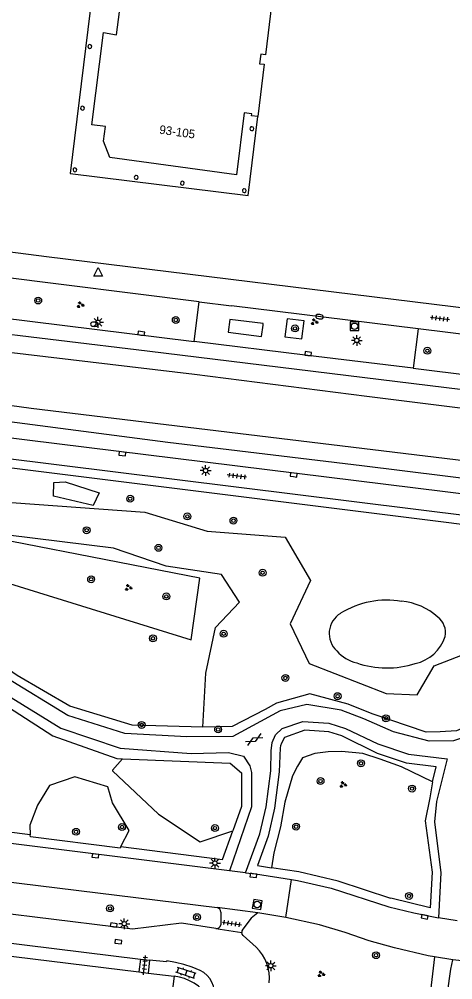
# Model space of a CAD drawing. Extents: x 131000 to 133014, y 396499 to 399001.
# Drawn here: x 131782.7 to 131833, y 396928.8 to 397040.1 of the extents above; entities that cross this region are included whole.
import ezdxf

# ---------------------------------------------------------------- set-up
doc = ezdxf.new("R2010")
doc.units = 0
for name, color, linetype in [('gg-anno-huisnummerreeks BGT', 7, 'Continuous'), ('gg-bbg-abri', 7, 'Continuous'), ('gg-bbg-hoofdgebouw', 7, 'Continuous'), ('gg-bbg-onder overbouw', 7, 'Continuous'), ('gg-bbg-pand overbouw', 7, 'Continuous'), ('gg-bbg-pilaar onder overbouw', 7, 'Continuous'), ('gg-knt-verharding', 7, 'Continuous'), ('gg-knt-verharding nz', 7, 'Continuous'), ('gt-grn-groengrens', 7, 'Continuous'), ('gt-grn-weggrens', 7, 'Continuous'), ('gt-symb-boom', 7, 'Continuous'), ('gt-symb-brandkraan', 7, 'Continuous'), ('gt-symb-gesloten verharding', 7, 'Continuous'), ('gt-symb-groenvak', 7, 'Continuous'), ('gt-symb-klinker verharding', 7, 'Continuous'), ('gt-symb-kolk', 7, 'Continuous'), ('gt-symb-lichtmast', 7, 'Continuous'), ('gt-symb-rioolschacht', 7, 'Continuous'), ('gt-symb-tegel verharding', 7, 'Continuous'), ('gt-symb-waterafsluiter', 7, 'Continuous')]:
    doc.layers.add(name, color=color, linetype=linetype)

# ---------------------------------------------------------------- blocks, each defined once
blk = doc.blocks.new('gt0-LMAST')
at = {"layer": 'gt-symb-lichtmast'}
for p, q in [((-0.18, 0.17), (-0.45, 0.44)), ((-0.01, 0.25), (-0.01, 0.62)), ((0.17, 0.17), (0.44, 0.44)), ((-0.26, 0), (-0.63, 0)), ((-0.18, -0.18), (-0.45, -0.45)), ((-0.01, -0.25), (-0.01, -0.63)), ((0.44, -0.45), (0.17, -0.18)), ((0.24, 0), (0.62, 0))]:
    blk.add_line(p, q, dxfattribs=at)
blk.add_circle((-0.01, 0), 0.25, dxfattribs=at)
blk = doc.blocks.new('gt0-GRVAK')
at = {"layer": 'gt-symb-groenvak'}
for p, q in [((-0.11, 0.19), (-0.23, 0.24)), ((-0.18, 0.15), (0.09, 0.15)), ((-0.09, 0.21), (-0.16, 0.32)), ((-0.05, 0.21), (-0.05, 0.39)), ((0, 0.21), (0.06, 0.32)), ((0.02, 0.19), (0.13, 0.24)), ((0.26, -0.05), (0.2, 0.06)), ((0.3, -0.05), (0.3, 0.13)), ((0.35, -0.05), (0.41, 0.06)), ((-0.24, -0.23), (-0.36, -0.18)), ((-0.32, -0.26), (-0.05, -0.26)), ((-0.23, -0.21), (-0.29, -0.09)), ((-0.18, -0.2), (-0.18, -0.02)), ((-0.14, -0.21), (-0.07, -0.09)), ((-0.12, -0.23), (0, -0.18)), ((0.24, -0.07), (0.12, -0.02)), ((0.17, -0.11), (0.44, -0.11)), ((0.37, -0.07), (0.49, -0.02))]:
    blk.add_line(p, q, dxfattribs=at)
blk = doc.blocks.new('gt0-BOOM')
at = {"layer": 'gt-symb-boom'}
for radius in [0.4, 0.2]:
    blk.add_circle((0, 0), radius, dxfattribs=at)
blk = doc.blocks.new('gt0-BR')
at = {"layer": 'gt-symb-brandkraan'}
for centre, radius, start, end in [((-0.24, 0), 0.206, 107.5669, 252.4331), ((0.6, -2.66), 3, 106.892, 107.5669), ((0, -0.69), 0.938, 73.108, 106.892), ((-0.6, -2.66), 3, 72.4331, 73.108), ((0.24, 0), 0.206, 287.567, 72.4331), ((0.6, 2.66), 3, 252.4331, 253.108), ((0, 0.69), 0.938, 253.108, 286.8921), ((-0.6, 2.66), 3, 286.8921, 287.567)]:
    blk.add_arc(centre, radius, start, end, dxfattribs=at)
blk = doc.blocks.new('gt0-WAFSL')
at = {"layer": 'gt-symb-waterafsluiter'}
for p, q in [((-0.5, -0.33), (0, 0.67)), ((0, 0.67), (0.5, -0.33)), ((0.5, -0.33), (-0.5, -0.33))]:
    blk.add_line(p, q, dxfattribs=at)
blk = doc.blocks.new('gt0-KOLK')
at = {"layer": 'gt-symb-kolk'}
blk.add_lwpolyline([(0, 0), (0.38, 0), (0.38, 0.4), (-0.38, 0.4), (-0.38, 0), (0, 0)], dxfattribs=at)
blk = doc.blocks.new('gt0-RS')
at = {"layer": 'gt-symb-rioolschacht'}
blk.add_lwpolyline([(-0.5, -0.5), (0.5, -0.5), (0.5, 0.5), (-0.5, 0.5)], close=True, dxfattribs=at)
blk.add_circle((0, 0), 0.375, dxfattribs=at)
blk = doc.blocks.new('gt0-TEG1')
at = {"layer": 'gt-symb-tegel verharding'}
for p, q in [((-1.12, 0), (1.12, 0)), ((-0.9, -0.25), (-0.9, 0.25)), ((-0.45, -0.25), (-0.45, 0.25)), ((0, -0.25), (0, 0.25)), ((0.45, -0.25), (0.45, 0.25)), ((0.9, -0.25), (0.9, 0.25))]:
    blk.add_line(p, q, dxfattribs=at)
blk = doc.blocks.new('gt0-GESVH1')
at = {"layer": 'gt-symb-gesloten verharding'}
for p, q in [((-0.99, -0.26), (0.01, 0.24)), ((0.01, -0.26), (-0.99, 0.24)), ((0.01, 0.24), (1.01, -0.26)), ((1.01, 0.24), (0.01, -0.26))]:
    blk.add_line(p, q, dxfattribs=at)
blk = doc.blocks.new('gt0-KL1')
at = {"layer": 'gt-symb-klinker verharding'}
for p, q in [((-1.15, 0.3), (1.15, 0.3)), ((-1, -0.3), (-1, 0.3)), ((-0.5, 0.3), (-0.5, 0.45)), ((0, -0.3), (0, 0.3)), ((0.5, 0.3), (0.5, 0.45)), ((1, -0.3), (1, 0.3)), ((-1.15, -0.3), (1.15, -0.3)), ((-0.5, -0.45), (-0.5, -0.3)), ((0.5, -0.45), (0.5, -0.3))]:
    blk.add_line(p, q, dxfattribs=at)

msp = doc.modelspace()

# ---------------------------------------------------------------- linework, layer by layer
at = {"layer": 'gg-bbg-abri'}
msp.add_lwpolyline([(131807.15, 397005.32), (131806.96, 397003.84), (131810.82, 397003.35), (131810.99, 397004.67), (131811.01, 397004.84), (131807.15, 397005.32)], dxfattribs=at)
at = {"layer": 'gg-bbg-hoofdgebouw'}
for p, q in [((131767.34, 396933.31), (131796.6, 396929.7)), ((131796.6, 396929.7), (131797.66, 396929.57)), ((131797.66, 396929.57), (131800.68, 396929.2))]:
    msp.add_line(p, q, dxfattribs=at)
for points in [[(131812.02, 397042.04), (131811.27, 397035.98), (131810.73, 397036.05), (131810.59, 397034.96), (131811.13, 397034.89), (131810.38, 397028.84)], [(131800.68, 396929.2), (131799.25, 396918.11), (131798.77, 396918.17)]]:
    msp.add_lwpolyline(points, dxfattribs=at)
at = {"layer": 'gg-bbg-onder overbouw'}
msp.add_lwpolyline([(131810.38, 397028.84), (131809.65, 397028.93), (131809.68, 397029.15), (131808.82, 397029.25), (131807.93, 397022.07), (131793.21, 397024.1), (131792.48, 397025.99), (131792.72, 397027.68), (131791.12, 397027.88), (131792.47, 397038.57), (131794.01, 397038.32), (131794.83, 397044.86), (131791.43, 397045.25)], dxfattribs=at)
at = {"layer": 'gg-bbg-pand overbouw'}
msp.add_lwpolyline([(131791.43, 397045.25), (131788.62, 397022.23), (131809.25, 397019.68), (131810.38, 397028.84)], dxfattribs=at)
at = {"layer": 'gg-bbg-pilaar onder overbouw'}
for points in [[(131790.68, 397036.92), (131790.74, 397036.78), (131790.88, 397036.72), (131791.01, 397036.74), (131791.09, 397036.82), (131791.12, 397036.98), (131791.05, 397037.11), (131790.9, 397037.17), (131790.8, 397037.14), (131790.7, 397037.05), (131790.68, 397036.92)], [(131789.83, 397029.78), (131789.89, 397029.64), (131790.03, 397029.58), (131790.15, 397029.6), (131790.24, 397029.68), (131790.27, 397029.84), (131790.21, 397029.97), (131790.05, 397030.03), (131789.95, 397030), (131789.85, 397029.91), (131789.83, 397029.78)], [(131809.46, 397027.4), (131809.52, 397027.26), (131809.66, 397027.2), (131809.79, 397027.22), (131809.87, 397027.3), (131809.91, 397027.46), (131809.84, 397027.59), (131809.68, 397027.65), (131809.59, 397027.63), (131809.49, 397027.53), (131809.46, 397027.4)], [(131788.95, 397022.64), (131789.01, 397022.5), (131789.15, 397022.44), (131789.28, 397022.46), (131789.36, 397022.54), (131789.4, 397022.7), (131789.33, 397022.83), (131789.17, 397022.89), (131789.08, 397022.86), (131788.98, 397022.77), (131788.95, 397022.64)], [(131796.06, 397021.76), (131796.13, 397021.62), (131796.27, 397021.56), (131796.39, 397021.58), (131796.47, 397021.66), (131796.51, 397021.82), (131796.44, 397021.95), (131796.29, 397022.01), (131796.19, 397021.99), (131796.09, 397021.89), (131796.06, 397021.76)], [(131801.41, 397021.09), (131801.47, 397020.95), (131801.61, 397020.89), (131801.74, 397020.91), (131801.82, 397020.99), (131801.86, 397021.15), (131801.79, 397021.28), (131801.63, 397021.34), (131801.54, 397021.31), (131801.44, 397021.22), (131801.41, 397021.09)], [(131808.59, 397020.22), (131808.65, 397020.08), (131808.79, 397020.02), (131808.92, 397020.04), (131809, 397020.12), (131809.04, 397020.28), (131808.97, 397020.41), (131808.81, 397020.47), (131808.71, 397020.45), (131808.62, 397020.35), (131808.59, 397020.22)]]:
    msp.add_lwpolyline(points, dxfattribs=at)
at = {"layer": 'gg-knt-verharding'}
for p, q in [((131779.6, 397013.4), (131785.87, 397012.63)), ((131785.87, 397012.63), (131888.33, 397000)), ((131803.58, 397007.37), (131779.28, 397010.39)), ((131803, 397002.78), (131803.58, 397007.37)), ((131778.69, 397005.77), (131803, 397002.78)), ((131828.99, 397004.22), (131828.42, 396999.67)), ((131862.8, 397000), (131828.99, 397004.22)), ((131828.42, 396999.67), (131909.2, 396989.58)), ((131841.83, 396984.14), (131767.81, 396993.27)), ((131844.27, 396981.37), (131761.45, 396991.65)), ((131807.11, 396941.43), (131738.35, 396949.96)), ((131739.57, 396945.3), (131805.67, 396937.18)), ((131808.97, 396941.19), (131807.11, 396941.43)), ((131810.39, 396936.55), (131805.67, 396937.18)), ((131806.09, 396936.63), (131806.08, 396935.16)), ((131810.39, 396936.55), (131809.61, 396935.93)), ((131813.63, 396936), (131810.39, 396936.55)), ((131833.49, 396935.64), (131831.35, 396935.96)), ((131767.52, 396934.78), (131796.78, 396931.18)), ((131805.5, 396934.72), (131808.52, 396934.28)), ((131796.78, 396931.18), (131796.6, 396929.7)), ((131796.78, 396931.18), (131797.84, 396931.07)), ((131797.84, 396931.07), (131797.66, 396929.57)), ((131832.99, 396931.1), (131830.88, 396931.44))]:
    msp.add_line(p, q, dxfattribs=at)
for points in [[(131815.76, 397005.15), (131813.78, 397005.4), (131813.52, 397003.31), (131815.51, 397003.07), (131815.76, 397005.15)], [(131828.42, 396999.67), (131816.2, 397001.15), (131803, 397002.78)], [(131835.21, 396957.16), (131833.1, 396956.47), (131830.27, 396956.46), (131826.12, 396957.52), (131822.7, 396959.05), (131820.05, 396960.02), (131816.09, 396960.68), (131812.97, 396959.95), (131807.49, 396956.97), (131802.17, 396956.96), (131794.95, 396957.35), (131788.34, 396959.42), (131781.27, 396963.74), (131771.08, 396970.75), (131767.88, 396972.61), (131763.63, 396974.11), (131761.04, 396974.46), (131753.69, 396974.89), (131752.86, 396975.03), (131752.02, 396975.68), (131749.21, 396979.07), (131745.92, 396982.2), (131741.52, 396985.79), (131737.71, 396988.71)], [(131738.35, 396949.96), (131738.68, 396953.84), (131740.33, 396959.15), (131741.9, 396961.76), (131747.45, 396967.65), (131751.5, 396972.19), (131752.23, 396972.76), (131753.27, 396973.02), (131760.89, 396972.73), (131763.39, 396972.36), (131767.3, 396970.95), (131770.15, 396969.43), (131780.41, 396962.31), (131787.52, 396957.96), (131794.4, 396955.63), (131802.65, 396955), (131806.98, 396955.12), (131808.74, 396954.69), (131809.44, 396953.6), (131809.66, 396952.8), (131809.67, 396948.84), (131807.11, 396941.43)], [(131808.97, 396941.19), (131810.63, 396945.71), (131811.34, 396948.82), (131811.91, 396953.01), (131811.92, 396955.33), (131812.06, 396956.3), (131812.45, 396957.17), (131813.21, 396957.91), (131815.62, 396958.72), (131818.62, 396958.52), (131820.55, 396957.91), (131824.32, 396956.15), (131827.88, 396954.92), (131832.35, 396954.39), (131831.1, 396949.44), (131830.88, 396947.1), (131831.62, 396941.2), (131831.35, 396935.96)], [(131805.5, 396934.72), (131801.54, 396935.35), (131795.86, 396934.64), (131793.65, 396934.94), (131779.78, 396936.61), (131765.39, 396938.41), (131748.03, 396940.53), (131739.12, 396941.64)], [(131808.97, 396941.19), (131810.13, 396941.05), (131814.31, 396940.4)], [(131814.31, 396940.4), (131814.97, 396940.3), (131818.88, 396939.42), (131825.59, 396937.26), (131828.49, 396936.55), (131831.35, 396935.96)], [(131809.61, 396935.93), (131808.64, 396934.64), (131808.55, 396934.47), (131808.52, 396934.28)], [(131830.88, 396931.44), (131830.16, 396931.56), (131826.23, 396932.49), (131823.31, 396933.31), (131820.5, 396934.27), (131817.55, 396935.14), (131813.63, 396936)], [(131810.18, 396932.57), (131808.7, 396933.92), (131808.58, 396934.08), (131808.52, 396934.28)], [(131803.69, 396929.88), (131802.78, 396930.25), (131801.82, 396930.57), (131800.84, 396930.8), (131799.82, 396930.97), (131799.8, 396930.86), (131797.84, 396931.07)], [(131830.88, 396931.44), (131830.35, 396926.86), (131830.08, 396925.9), (131829.86, 396925.36), (131829.28, 396924.53), (131829, 396924.29), (131828.1, 396923.85), (131827.52, 396923.73), (131826.52, 396923.66), (131824.42, 396923.7), (131823.42, 396923.67), (131821.89, 396923.48), (131818.65, 396922.79), (131817.12, 396922.35), (131815.24, 396921.64), (131813.14, 396920.76), (131812.2, 396920.42), (131810.68, 396920.02)], [(131832.39, 396927.28), (131832.79, 396930.03), (131832.99, 396931.1)], [(131862.73, 396928.64), (131855.05, 396929.53), (131847.13, 396930.19), (131837.11, 396930.63), (131832.99, 396931.1)]]:
    msp.add_lwpolyline(points, dxfattribs=at)
for centre, radius, start, end in [((131805.54, 396936.65), 0.548, 358.3441, 76.3268), ((131805.56, 396935.25), 0.536, 263.6922, 349.8596), ((131806.84, 396928.99), 4.9, 353.5418, 46.9028), ((131802.26, 396927.06), 3.16, 351.3081, 63.1233), ((131800.08, 396923.71), 5.52, 32.1837, 83.7093)]:
    msp.add_arc(centre, radius, start, end, dxfattribs=at)
at = {"layer": 'gg-knt-verharding nz'}
for p in [(131803.58, 397007.37), (131828.99, 397004.22)]:
    msp.add_line(p, (131807.34, 397006.9), dxfattribs=at)
for points in [[(131922.17, 396984.16), (131898.19, 396987.15), (131862.26, 396991.48), (131823.02, 396996.37), (131803.04, 396998.92), (131781.2, 397001.53), (131759.6, 397004.25), (131755.25, 397005.14), (131750.75, 397007.09), (131748.18, 397008.55), (131746.64, 397009.7)], [(131922.39, 396986.15), (131897.98, 396989.16), (131836.06, 396996.94), (131797.55, 397001.63), (131777.01, 397004.1), (131771.25, 397004.91), (131759.88, 397006.45), (131757.89, 397007.26), (131754.52, 397008.75)], [(131755.16, 396994.91), (131758.18, 396996.49), (131761.76, 396997.54), (131764.5, 396997.74), (131784.09, 396995.03), (131839.38, 396988.35), (131854.84, 396986.33), (131886.56, 396982.24), (131921.48, 396977.98)], [(131767.81, 396993.27), (131768.34, 396993.82), (131769.24, 396994.28), (131771.35, 396994.67), (131773.55, 396994.55), (131799.95, 396991.11), (131822.44, 396988.39), (131861.11, 396983.6), (131900.83, 396978.47), (131924.74, 396975.54)]]:
    msp.add_lwpolyline(points, dxfattribs=at)
at = {"layer": 'gt-grn-groengrens'}
for points in [[(131838.44, 396959.81), (131854.39, 396966.37), (131856.4, 396967.1), (131856.33, 396967.53), (131856.17, 396968.26), (131843.94, 396980.32), (131799.8, 396985.85), (131762.05, 396990.54), (131761.5, 396990.59), (131759.61, 396990.09), (131757.42, 396989.87), (131754.2, 396990.09), (131750.73, 396990.28), (131748.12, 396990.39), (131747.03, 396990.37)], [(131804.02, 396958.06), (131795.81, 396958.29), (131788.59, 396960.5), (131782.49, 396964.06), (131772.6, 396970.85), (131768.84, 396973.33), (131764.36, 396975.04), (131763.57, 396975.17), (131755.29, 396975.9), (131753.48, 396976), (131753.15, 396976), (131749.36, 396980.32), (131746.82, 396982.72), (131740.3, 396987.88), (131742, 396989.54)], [(131786.67, 396984.82), (131786.72, 396986.42), (131788.04, 396986.5), (131791.98, 396985.21), (131791.3, 396983.75), (131786.67, 396984.82)], [(131804.02, 396958.06), (131804.37, 396964.33), (131805.48, 396969.62), (131808.27, 396972.55), (131806.18, 396975.76), (131799.77, 396976.73), (131793.65, 396978.82), (131781.43, 396980.33), (131778.33, 396981.33), (131778.46, 396983.28), (131781.81, 396984.12), (131797.27, 396983), (131804.51, 396980.77), (131813.56, 396980.08), (131816.49, 396975.06), (131814.12, 396970.04), (131816.35, 396965.44), (131825.26, 396961.96), (131828.88, 396961.82), (131830.83, 396965.16), (131836.54, 396967.39), (131837.64, 396963.54), (131838.44, 396959.81)], [(131802.66, 396968.19), (131803.65, 396975.34), (131770.72, 396981.73), (131771.05, 396977.95), (131802.66, 396968.19)], [(131751.96, 396970.07), (131752.9, 396971.55), (131754.16, 396971.76), (131763.07, 396971.21), (131766.41, 396970.09), (131769.82, 396968.14), (131777.61, 396962.85), (131786.59, 396957.08), (131794.04, 396954.43), (131794.7, 396954.41)], [(131838.44, 396959.81), (131835.37, 396958.49), (131833.43, 396957.63), (131831.55, 396957.54), (131829.9, 396957.47), (131823.63, 396959.61), (131820.87, 396960.73), (131816.41, 396961.92), (131812.56, 396960.83), (131811.24, 396960.11), (131807.41, 396958.16), (131804.02, 396958.06)], [(131830.65, 396951.73), (131831.06, 396953.47), (131827.65, 396953.89), (131824.26, 396955.01), (131820.12, 396957.06), (131818.62, 396957.51), (131815.84, 396957.7), (131813.49, 396956.88), (131813.14, 396956.22), (131813, 396955.9), (131812.97, 396955.69), (131812.85, 396952.9), (131812.31, 396948.66), (131811.58, 396945.45), (131810.35, 396942.03), (131811.98, 396941.75)], [(131830.65, 396951.73), (131827.05, 396953.46), (131824.56, 396954.37), (131822.55, 396955), (131820.11, 396955.24), (131818.53, 396955.19), (131817, 396955), (131815.57, 396954.52), (131814.99, 396953.56), (131814.42, 396952.41), (131813.51, 396949.39), (131813.03, 396946.52), (131812.26, 396943.51), (131811.98, 396941.75)], [(131794.7, 396954.41), (131793.51, 396953.08), (131793.52, 396953.02), (131798.86, 396947.98), (131803.69, 396944.78), (131807.49, 396946.06)], [(131794.7, 396954.41), (131807.19, 396953.88), (131808.51, 396952.76), (131808.51, 396948.86), (131807.49, 396946.06)], [(131794.51, 396944.24), (131795.48, 396946.08), (131793.52, 396949.28), (131792.99, 396951.14), (131789.17, 396952.3), (131786.24, 396951.32), (131784.82, 396949.01), (131783.93, 396946.7), (131783.99, 396945.58)], [(131830.65, 396951.73), (131830.32, 396949.89), (131829.8, 396947.2), (131830.59, 396941.26), (131830.39, 396937.13), (131825.8, 396938.24), (131825.8, 396938.22), (131819.72, 396940.23), (131815.15, 396941.3), (131811.98, 396941.75)], [(131783.99, 396945.58), (131764.74, 396948.03), (131750.55, 396949.76)], [(131794.51, 396944.24), (131794.4, 396944.05), (131784.01, 396945.34), (131783.99, 396945.58)], [(131794.51, 396944.24), (131806.29, 396942.74), (131807.49, 396946.06)]]:
    msp.add_lwpolyline(points, dxfattribs=at)
for centre, radius, start, end in [((131825.37, 396962.57), 10.22, 80.4492, 121.7404), ((131826.44, 396965.47), 7.21, 47.9588, 85.06), ((131821.38, 396968.92), 2.72, 120.7917, 227.6333), ((131829.9, 396969.02), 2.26, 348.8377, 52.7839), ((131827.71, 396969.97), 4.62, 281.7365, 342.5586), ((131822.92, 396969.87), 4.49, 221.2302, 256.356), ((131825.35, 396975.65), 10.72, 251.0125, 287.9241)]:
    msp.add_arc(centre, radius, start, end, dxfattribs=at)
at = {"layer": 'gt-grn-weggrens'}
msp.add_line((131813.63, 396936), (131814.31, 396940.4), dxfattribs=at)

# ---------------------------------------------------------------- block references
at = {"layer": 'gt-symb-boom'}
for p in [(131784.91, 397007.51), (131800.87, 397005.25), (131814.7, 397004.28), (131830.06, 397001.69), (131802.22, 396982.49), (131790.53, 396980.89), (131791.05, 396975.21), (131810.94, 396975.96), (131799.78, 396973.22), (131798.22, 396968.36), (131806.42, 396968.89), (131813.59, 396963.77), (131819.64, 396961.66), (131796.91, 396958.32), (131825.25, 396959.09), (131805.78, 396957.8), (131822.35, 396953.88), (131817.66, 396951.82), (131828.28, 396950.95), (131789.3, 396945.94), (131794.63, 396946.49), (131805.41, 396946.37), (131814.83, 396946.54), (131827.93, 396938.51), (131793.25, 396937.06), (131803.33, 396936.05), (131824.1, 396931.64)]:
    msp.add_blockref('gt0-BOOM', p, dxfattribs=at)
for p, rotation in [((131795.58, 396984.54), -113.46200022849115), ((131807.56, 396982), -113.46200022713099), ((131798.86, 396978.85), -113.4620002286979)]:
    msp.add_blockref('gt0-BOOM', p, dxfattribs=dict(at, rotation=rotation))
at = {"layer": 'gt-symb-brandkraan', "rotation": -7.4202754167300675}
msp.add_blockref('gt0-BR', (131817.54, 397005.64), dxfattribs=at)
at = {"layer": 'gt-symb-brandkraan'}
msp.add_blockref('gt0-BR', (131791.41, 397004.76), dxfattribs=at)
at = {"layer": 'gt-symb-gesloten verharding', "rotation": 28.487007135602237}
msp.add_blockref('gt0-GESVH1', (131809.96, 396956.63), dxfattribs=at)
at = {"layer": 'gt-symb-groenvak'}
for p in [(131789.79, 397007.01), (131816.94, 397005.04), (131795.37, 396974.24), (131820.27, 396951.4), (131817.72, 396929.45)]:
    msp.add_blockref('gt0-GRVAK', p, dxfattribs=at)
at = {"layer": 'gt-symb-klinker verharding', "rotation": 161.5106736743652}
msp.add_blockref('gt0-KL1', (131802.05, 396929.58), dxfattribs=at)
at = {"layer": 'gt-symb-kolk'}
for p, rotation in [((131796.83, 397003.51), -8.27589282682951), ((131816.2, 397001.15), -6.890548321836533), ((131794.65, 396989.56), -6.947410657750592), ((131814.52, 396987.1), -7.238726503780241), ((131791.57, 396943.35), 173.10945167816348), ((131809.9, 396941.08), 172.70443985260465), ((131829.77, 396936.29), 168.11724113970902), ((131793.65, 396934.94), -7.583444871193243), ((131794.18, 396933), -7.004259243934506)]:
    msp.add_blockref('gt0-KOLK', p, dxfattribs=dict(at, rotation=rotation))
at = {"layer": 'gt-symb-lichtmast'}
for p in [(131791.85, 397004.99), (131821.87, 397002.88), (131804.34, 396987.81), (131805.42, 396942.31), (131794.91, 396935.29), (131811.9, 396930.41)]:
    msp.add_blockref('gt0-LMAST', p, dxfattribs=at)
at = {"layer": 'gt-symb-rioolschacht'}
msp.add_blockref('gt0-RS', (131821.61, 397004.53), dxfattribs=at)
at = {"layer": 'gt-symb-rioolschacht', "rotation": -9.029198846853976}
msp.add_blockref('gt0-RS', (131810.32, 396937.51), dxfattribs=at)
at = {"layer": 'gt-symb-tegel verharding'}
for p, rotation in [((131831.52, 397005.43), -7.068140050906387), ((131807.96, 396987.16), 172.93185994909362), ((131807.38, 396935.31), -7.87092049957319), ((131797.25, 396930.47), 84.43197594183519)]:
    msp.add_blockref('gt0-TEG1', p, dxfattribs=dict(at, rotation=rotation))
at = {"layer": 'gt-symb-waterafsluiter'}
msp.add_blockref('gt0-WAFSL', (131791.88, 397010.65), dxfattribs=at)

# ---------------------------------------------------------------- texts
at = {"layer": 'gg-anno-huisnummerreeks BGT'}
msp.add_text('93-105', height=1, rotation=352.1, dxfattribs=at).set_placement((131798.91, 397026.85))

doc.saveas('drawing.dxf')
